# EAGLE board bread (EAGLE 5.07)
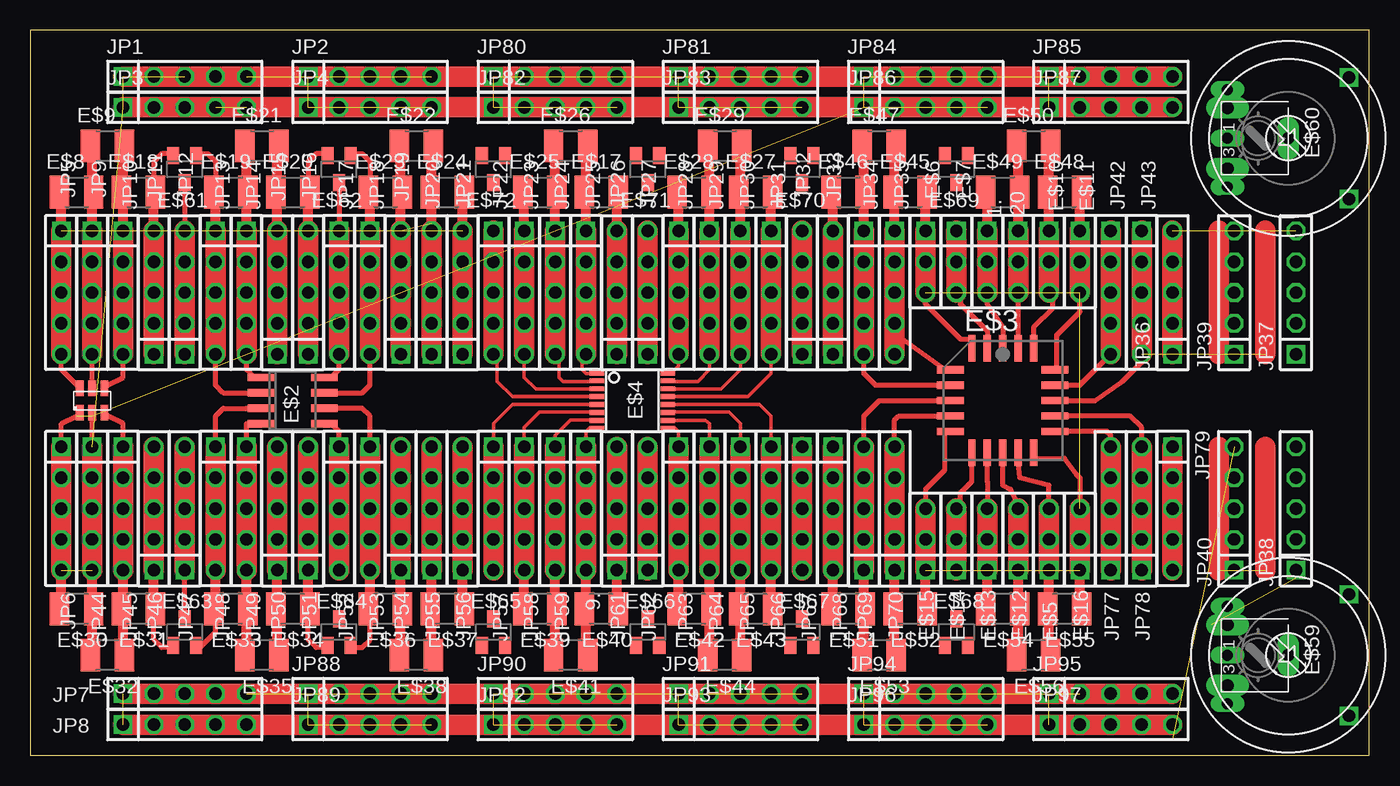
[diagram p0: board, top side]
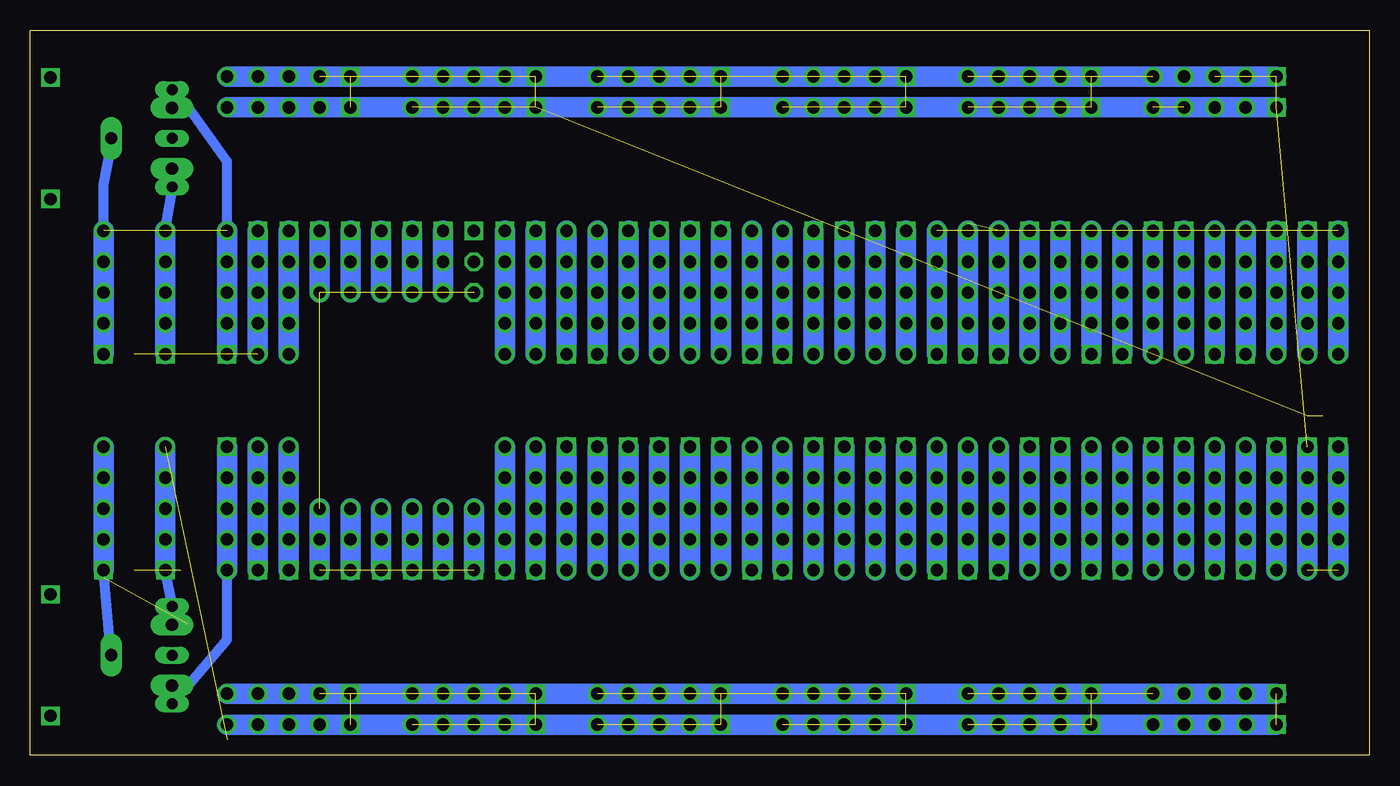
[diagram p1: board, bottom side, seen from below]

Size 110.16 x 59.68 mm. Coordinates in mm from the lower left corner, seen from the top.
Outline: 0,0 110.16,0 110.16,59.68 0,59.68 0,0
Copper layers (1*16): Top 0.035mm / dielectric 1.5mm / Bottom 0.035mm
Design rules "default": minimum track width 10mil, minimum drill 24mil, track to track 8mil, track to pad 8mil, pad to pad 8mil, via to via 8mil, smd to smd 8mil, copper to edge 40mil, drill to drill 8mil, minimum pad ring 10mil, minimum via ring 8mil, stop-mask expansion 4mil, vias tented up to drill 0mil, thermal gap 10mil

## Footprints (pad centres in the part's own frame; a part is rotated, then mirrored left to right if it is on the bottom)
1X03 = drill 1.016 square: 1 -2.54,0 | drill 1.016 octagon: 2 0,0; 3 2.54,0
1X05 = drill 1.016 square: 1 -5.08,0 | drill 1.016 octagon: 2 -2.54,0; 3 0,0; 4 2.54,0; 5 5.08,0
SOT23-6 = smd 0.635 x 1.27: 1 -1.016,-1.016; 2 0,-1.016; 3 1.016,-1.016; 4 1.016,1.016; 5 0,1.016; 6 -1.016,1.016
SO08 = smd 0.6 x 2.2: 1 -1.905,-2.6; 2 -0.635,-2.6; 3 0.635,-2.6; 4 1.905,-2.6; 5 1.905,2.6; 6 0.635,2.6; 7 -0.635,2.6; 8 -1.905,2.6
PLCC20S = smd 0.6 x 2.2: 1 0,4.3; 2 -1.27,4.3; 3 -2.54,4.3; 9 -2.54,-4.3; 10 -1.27,-4.3; 11 0,-4.3; 12 1.27,-4.3; 13 2.54,-4.3; 19 2.54,4.3; 20 1.27,4.3 | smd 2.2 x 0.6: 4 -4.3,2.54; 5 -4.3,1.27; 6 -4.3,0; 7 -4.3,-1.27; 8 -4.3,-2.54; 14 4.3,-2.54; 15 4.3,-1.27; 16 4.3,0; 17 4.3,1.27; 18 4.3,2.54
SSOP16 = smd 0.4 x 1.2: 1 -2.275,-2.925; 2 -1.625,-2.925; 3 -0.975,-2.925; 4 -0.325,-2.925; 5 0.325,-2.925; 6 0.975,-2.925; 7 1.625,-2.925; 8 2.275,-2.925; 9 2.275,2.925; 10 1.625,2.925; 11 0.975,2.925; 12 0.325,2.925; 13 -0.325,2.925; 14 -0.975,2.925; 15 -1.625,2.925; 16 -2.275,2.925
R1210 = smd 1.6 x 2.7: 1 -1.4,0; 2 1.4,0
RANDL = drill 0.9 long: A -4,5; E 4,5; S 0,5 | drill 1 square: P$1 -5,-5; P$2 5,-5
EVND8AA = drill 1 pad 1.778 long: A -2.5,-2.5; E 2.5,-2.5; S 0,2.5
SOT23 = smd 1 x 1.4: 1 -0.95,-1.1; 2 0.95,-1.1; 3 0,1.1

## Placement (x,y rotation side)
1.  [1X03]  78.74,40.64 270 top
9.  [1X05]  45.72,20.32 270 top
20  [1X03]  81.28,40.64 270 top
E$1  [SOT23-6]  5.08,29.21 0 top
E$2  [SO08]  21.59,29.21 270 top
E$3  [PLCC20S]  80.01,29.21 0 top
E$4  [SSOP16]  49.53,29.21 270 top
E$5  [1X03]  83.82,17.78 90 top
E$6  [1X03]  73.66,40.64 270 top
E$7  [1X03]  76.2,40.64 270 top
E$8  [R1210]  3.81,46.35 0 top
E$9  [R1210]  6.35,50.16 0 top
E$10  [1X03]  83.82,40.64 270 top
E$11  [1X03]  86.36,40.64 270 top
E$12  [1X03]  81.28,17.78 90 top
E$13  [1X03]  78.74,17.78 90 top
E$14  [1X03]  76.2,17.78 90 top
E$15  [1X03]  73.66,17.78 90 top
E$16  [1X03]  86.36,17.78 90 top
E$17  [R1210]  46.99,46.35 0 top
E$18  [R1210]  8.89,46.35 0 top
E$19  [R1210]  16.51,46.35 0 top
E$20  [R1210]  21.59,46.35 0 top
E$21  [R1210]  19.05,50.16 0 top
E$22  [R1210]  31.75,50.16 0 top
E$23  [R1210]  29.21,46.35 0 top
E$24  [R1210]  34.29,46.35 0 top
E$25  [R1210]  41.91,46.35 0 top
E$26  [R1210]  44.45,50.16 0 top
E$27  [R1210]  59.69,46.35 0 top
E$28  [R1210]  54.61,46.35 0 top
E$29  [R1210]  57.15,50.16 0 top
E$30  [R1210]  3.81,12.06 180 top
E$31  [R1210]  8.89,12.06 180 top
E$32  [R1210]  6.35,8.26 180 top
E$33  [R1210]  16.51,12.06 180 top
E$34  [R1210]  21.59,12.06 180 top
E$35  [R1210]  19.05,8.26 180 top
E$36  [R1210]  29.21,12.06 180 top
E$37  [R1210]  34.29,12.06 180 top
E$38  [R1210]  31.75,8.26 180 top
E$39  [R1210]  41.91,12.06 180 top
E$40  [R1210]  46.99,12.06 180 top
E$41  [R1210]  44.45,8.26 180 top
E$42  [R1210]  54.61,12.06 180 top
E$43  [R1210]  59.69,12.06 180 top
E$44  [R1210]  57.15,8.26 180 top
E$45  [R1210]  72.39,46.35 0 top
E$46  [R1210]  67.31,46.35 0 top
E$47  [R1210]  69.85,50.16 0 top
E$48  [R1210]  85.09,46.35 0 top
E$49  [R1210]  80.01,46.35 0 top
E$50  [R1210]  82.55,50.16 0 top
E$51  [R1210]  67.31,12.06 180 top
E$52  [R1210]  72.39,12.06 180 top
E$53  [R1210]  69.85,8.26 180 top
E$54  [R1210]  80.01,12.06 180 top
E$55  [R1210]  85.09,12.06 180 top
E$56  [R1210]  82.55,8.26 180 top
E$57  [RANDL]  103.5,50.8 90 top
E$58  [RANDL]  103.5,8.26 90 top
E$59  [EVND8AA]  101.02,8.26 270 top
E$60  [EVND8AA]  101.02,50.8 270 top
E$61  [SOT23]  12.7,48.26 180 top
E$62  [SOT23]  25.4,48.26 180 top
E$63  [SOT23]  12.7,10.16 0 top
E$64  [SOT23]  25.4,10.16 0 top
E$65  [SOT23]  38.1,10.16 0 top
E$66  [SOT23]  50.8,10.16 0 top
E$67  [SOT23]  63.5,10.16 0 top
E$68  [SOT23]  76.2,10.16 0 top
E$69  [SOT23]  76.2,48.26 180 top
E$70  [SOT23]  63.5,48.26 180 top
E$71  [SOT23]  50.8,48.26 180 top
E$72  [SOT23]  38.1,48.26 180 top
JP1  [1X05]  12.7,55.88 0 top
JP2  [1X05]  27.94,55.88 0 top
JP3  [1X05]  12.7,53.34 0 top
JP4  [1X05]  27.94,53.34 0 top
JP5  [1X05]  2.54,38.1 270 top
JP6  [1X05]  2.54,20.32 270 top
JP7  [1X05]  12.7,5.08 0 top
JP8  [1X05]  12.7,2.54 0 top
JP9  [1X05]  5.08,38.1 270 top
JP10  [1X05]  7.62,38.1 270 top
JP11  [1X05]  10.16,38.1 90 top
JP12  [1X05]  12.7,38.1 90 top
JP13  [1X05]  15.24,38.1 270 top
JP14  [1X05]  17.78,38.1 270 top
JP15  [1X05]  20.32,38.1 90 top
JP16  [1X05]  22.86,38.1 90 top
JP17  [1X05]  25.4,38.1 270 top
JP18  [1X05]  27.94,38.1 270 top
JP19  [1X05]  30.48,38.1 90 top
JP20  [1X05]  33.02,38.1 90 top
JP21  [1X05]  35.56,38.1 90 top
JP22  [1X05]  38.1,38.1 270 top
JP23  [1X05]  40.64,38.1 270 top
JP24  [1X05]  43.18,38.1 270 top
JP25  [1X05]  45.72,38.1 270 top
JP26  [1X05]  48.26,38.1 90 top
JP27  [1X05]  50.8,38.1 90 top
JP28  [1X05]  53.34,38.1 270 top
JP29  [1X05]  55.88,38.1 270 top
JP30  [1X05]  58.42,38.1 270 top
JP31  [1X05]  60.96,38.1 270 top
JP32  [1X05]  63.5,38.1 90 top
JP33  [1X05]  66.04,38.1 90 top
JP34  [1X05]  68.58,38.1 270 top
JP35  [1X05]  71.12,38.1 270 top
JP36  [1X05]  93.98,38.1 90 top
JP37  [1X05]  104.14,38.1 90 top
JP38  [1X05]  104.14,20.32 90 top
JP39  [1X05]  99.06,38.1 90 top
JP40  [1X05]  99.06,20.32 90 top
JP42  [1X05]  88.9,38.1 270 top
JP43  [1X05]  91.44,38.1 270 top
JP44  [1X05]  5.08,20.32 270 top
JP45  [1X05]  7.62,20.32 270 top
JP46  [1X05]  10.16,20.32 90 top
JP47  [1X05]  12.7,20.32 90 top
JP48  [1X05]  15.24,20.32 270 top
JP49  [1X05]  17.78,20.32 270 top
JP50  [1X05]  20.32,20.32 90 top
JP51  [1X05]  22.86,20.32 90 top
JP52  [1X05]  25.4,20.32 270 top
JP53  [1X05]  27.94,20.32 270 top
JP54  [1X05]  30.48,20.32 90 top
JP55  [1X05]  33.02,20.32 90 top
JP56  [1X05]  35.56,20.32 90 top
JP57  [1X05]  38.1,20.32 270 top
JP58  [1X05]  40.64,20.32 270 top
JP59  [1X05]  43.18,20.32 270 top
JP61  [1X05]  48.26,20.32 90 top
JP62  [1X05]  50.8,20.32 90 top
JP63  [1X05]  53.34,20.32 270 top
JP64  [1X05]  55.88,20.32 270 top
JP65  [1X05]  58.42,20.32 270 top
JP66  [1X05]  60.96,20.32 270 top
JP67  [1X05]  63.5,20.32 270 top
JP68  [1X05]  66.04,20.32 270 top
JP69  [1X05]  68.58,20.32 90 top
JP70  [1X05]  71.12,20.32 90 top
JP77  [1X05]  88.9,20.32 90 top
JP78  [1X05]  91.44,20.32 90 top
JP79  [1X05]  93.98,20.32 270 top
JP80  [1X05]  43.18,55.88 0 top
JP81  [1X05]  58.42,55.88 0 top
JP82  [1X05]  43.18,53.34 0 top
JP83  [1X05]  58.42,53.34 0 top
JP84  [1X05]  73.66,55.88 0 top
JP85  [1X05]  88.9,55.88 0 top
JP86  [1X05]  73.66,53.34 0 top
JP87  [1X05]  88.9,53.34 0 top
JP88  [1X05]  27.94,5.08 0 top
JP89  [1X05]  27.94,2.54 0 top
JP90  [1X05]  43.18,5.08 0 top
JP91  [1X05]  58.42,5.08 0 top
JP92  [1X05]  43.18,2.54 0 top
JP93  [1X05]  58.42,2.54 0 top
JP94  [1X05]  73.66,5.08 0 top
JP95  [1X05]  88.9,5.08 0 top
JP96  [1X05]  73.66,2.54 0 top
JP97  [1X05]  88.9,2.54 0 top

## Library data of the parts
1. 9. 20 E$5-E$7 E$10-E$16 JP1-JP40 JP42-JP59 JP61-JP70 JP77-JP97 = pinhead(2)
E$1 = microchip-5
E$2-E$4 = linear
E$8 E$9 E$17-E$56 = rcl
E$57-E$60 = pot
E$61-E$72 = transistor-npn

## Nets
N$1: JP1.1 JP1.2 JP1.3
N$2: JP2.1 JP2.2
N$3: JP3.4 JP3.5
N$76: JP80.1 JP80.2 JP80.3
N$77: JP81.1 JP81.2
N$78: JP82.4 JP82.5
N$80: JP84.1 JP84.2 JP84.3
N$81: JP85.1 JP85.2
N$82: JP86.4 JP86.5
N$84: JP88.1 JP88.2
N$86: JP90.1 JP90.2 JP90.3
N$87: JP91.1 JP91.2
N$88: JP92.4 JP92.5
N$90: JP94.1 JP94.2 JP94.3
N$91: JP95.1 JP95.2
N$92: JP96.4 JP96.5
S$25: 20.3
S$30: E$7.3
S$31: E$6.3
S$42: E$5.1
S$43: E$14.3

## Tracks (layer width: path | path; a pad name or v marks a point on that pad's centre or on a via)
N$1  (2 unrouted)
N$2  (1 unrouted)
N$3  (1 unrouted)
N$4  (4 unrouted)
  Top 0.406: 3.81,30.48 2.54,31.75 2.54,33.02 | 26.67,49.53 27.3,49.53 27.94,48.9 27.94,46.35 | 24.13,49.53 23.5,49.53 22.86,48.9 22.86,46.35 | 13.97,49.53 14.61,49.53 15.24,48.9 15.24,46.35
  Top 0.813: 2.54,43.18 2.54,46.35 | 15.24,43.18 15.24,46.35 | 22.86,43.18 22.86,46.35 | 27.94,43.18 27.94,46.35 | 35.56,43.18 35.56,46.35
  Top 1.676: 2.54,33.02 2.54,43.18
N$5  (4 unrouted)
  Top 0.406: 5.08,30.48 5.08,33.02
  Top 0.813: 5.08,43.18 5.08,49.53 | 17.78,43.18 17.78,49.53 | 20.32,43.18 20.32,49.53 | 30.48,43.18 30.48,49.53 | 33.02,43.81 33.02,50.16
  Top 1.676: 5.08,33.02 5.08,43.18
N$6
  Top 0.406: 6.35,30.48 7.62,31.11 7.62,33.02
  Top 0.813: 7.62,43.18 7.62,49.53
  Top 1.676: 7.62,33.02 7.62,43.18
N$7  (3 unrouted)
  Top 0.406: 85.09,29.21 87.63,29.21 89.85,30.8 91.44,32.38 91.44,33.02
  Top 1.676: 91.44,33.02 91.44,43.18 | 93.98,33.02 93.98,43.18 | 97.79,33.02 97.79,43.18 | 101.6,33.02 101.6,43.18
N$8
  Top 1.676: 88.9,33.02 88.9,43.18
N$9
  Top 0.813: 40.64,43.18 40.64,46.35
N$10
  Top 0.813: 43.18,43.18 43.18,49.53
N$11
  Top 0.813: 45.72,43.18 45.72,49.53
N$12
  Top 0.813: 48.26,43.18 48.26,46.35
N$13
  Top 0.813: 53.34,43.18 53.34,46.35
N$14
  Top 0.813: 55.88,43.18 55.88,49.53
N$15
  Top 0.305: 71.44,37.15 71.12,37.47 71.12,38.1
  Top 0.406: 75.25,31.75 71.75,34.29 71.44,37.15
  Top 1.676: 71.12,33.02 71.12,38.1 71.12,43.18
N$16
  Top 0.813: 58.42,43.18 58.42,49.53
N$17
  Top 0.813: 60.96,43.18 60.96,46.35
N$18
  Top 0.406: 12.06,8.89 10.79,8.89 10.16,9.53 10.16,12.7
  Top 0.813: 10.16,12.06 10.16,12.7 10.16,15.24
N$19
  Top 1.676: 60.96,33.02 60.96,43.18
N$20
  Top 0.305: 52.7,30.16 56.83,30.16 58.42,31.75 58.42,33.02
  Top 1.676: 58.42,33.02 58.42,43.18
N$21
  Top 0.305: 52.7,30.8 54.93,30.8 55.88,31.75 55.88,33.02
  Top 1.676: 55.88,33.02 55.88,43.18
N$22
  Top 1.676: 53.34,33.02 53.34,43.18
N$23
  Top 1.676: 50.8,33.02 50.8,43.18
N$24
  Top 1.676: 48.26,33.02 48.26,43.18
N$25
  Top 0.305: 46.04,31.43 45.72,31.43 45.4,31.75 45.4,32.7 45.72,33.02
  Top 1.676: 45.72,33.02 45.72,43.18
N$26
  Top 0.305: 46.04,30.8 43.81,30.8 43.5,31.11 43.5,32.7 43.18,33.02
  Top 1.676: 43.18,33.02 43.18,43.18
N$27
  Top 0.305: 46.04,30.16 41.59,30.16 40.64,31.11 40.64,33.02
  Top 1.676: 40.64,33.02 40.64,43.18
N$28
  Top 0.305: 46.35,29.53 39.69,29.53 38.42,30.8 38.42,32.7 38.1,33.02
  Top 1.676: 38.1,33.02 38.1,43.18
N$29
  Top 1.676: 35.56,33.02 35.56,43.18
N$30
  Top 1.676: 33.02,33.02 33.02,43.18
N$31
  Top 1.676: 30.48,33.02 30.48,43.18
N$32
  Top 0.406: 24.77,29.84 27.3,29.84 27.94,30.48 27.94,33.02
  Top 1.676: 27.94,33.02 27.94,43.18
N$33
  Top 0.406: 24.77,31.11 25.4,31.75 25.4,33.02 | 25.4,46.99 25.4,43.18
  Top 1.676: 25.4,33.02 25.4,43.18
N$34
  Top 1.676: 22.86,33.02 22.86,43.18
N$35
  Top 1.676: 20.32,33.02 20.32,43.18
N$36
  Top 0.406: 18.41,31.11 17.78,31.75 17.78,33.02
  Top 1.676: 17.78,33.02 17.78,43.18
N$37
  Top 0.406: 18.41,29.84 15.88,29.84 15.24,30.48 15.24,33.02
  Top 1.676: 15.24,33.02 15.24,43.18
N$38
  Top 0.406: 12.7,46.35 12.7,43.18
  Top 1.676: 12.7,33.02 12.7,43.18
N$39
  Top 0.406: 11.43,49.53 10.79,49.53 10.16,48.9 10.16,45.72
  Top 0.813: 10.16,43.18 10.16,45.72 10.16,46.35
  Top 1.676: 10.16,33.02 10.16,43.18
N$40  (5 unrouted)
  Top 0.406: 3.81,27.94 2.54,27.3 2.54,25.4 | 5.08,25.4 5.08,27.94
  Top 1.676: 5.08,15.24 5.08,25.4 | 83.82,55.88 93.98,55.88 | 83.82,53.34 93.98,53.34 | 68.58,53.34 78.74,53.34 | 68.58,55.88 78.74,55.88 | 2.54,15.24 2.54,25.4
N$41
  Top 1.676: 93.98,15.24 93.98,25.4
N$42
  Top 0.406: 85.41,27.94 90.49,27.94 91.44,26.99 91.44,25.08
  Top 1.676: 91.44,15.24 91.44,25.08 91.44,25.4
N$43
  Top 0.406: 85.41,26.67 88.58,26.67 88.9,26.35 88.9,25.4
  Top 1.676: 88.9,15.24 88.9,25.4
N$44
  Top 0.813: 7.62,8.89 7.62,15.24
N$45
  Top 0.406: 82.55,24.45 85.09,24.45 86.04,23.18 86.36,22.86 86.36,20.64
N$46
  Top 0.813: 5.08,8.89 5.08,15.24
N$47
  Top 0.406: 80.01,23.81 80.01,22.23 80.64,21.91 81.28,20.64
N$48
  Top 0.406: 78.74,24.13 78.74,22.54 78.74,20.64
N$49
  Top 0.813: 2.54,12.06 2.54,15.24
N$50
  Top 0.305: 71.12,25.4 71.12,25.72
  Top 0.406: 74.93,27.94 71.44,27.94 71.12,27.62 71.12,25.72
  Top 1.676: 71.12,15.24 71.12,25.4
N$51
  Top 0.406: 74.93,29.21 69.85,29.21 68.58,27.94 68.58,25.4
  Top 1.676: 68.58,15.24 68.58,25.4
N$52
  Top 1.676: 66.04,15.24 66.04,25.4
N$53
  Top 1.676: 63.5,15.24 63.5,25.4
N$54
  Top 1.676: 60.96,15.24 60.96,25.4
N$55
  Top 0.305: 52.39,28.26 57.47,28.26 58.42,27.3 58.42,25.4
  Top 1.676: 58.42,15.24 58.42,25.4
N$56
  Top 0.305: 52.7,27.56 55.56,27.56 55.88,27.3 55.88,25.4
  Top 1.676: 55.88,15.24 55.88,25.4
N$57
  Top 0.305: 53.02,26.99 53.34,26.67 53.34,25.08
  Top 1.676: 53.34,15.24 53.34,25.08 53.34,25.4
N$58
  Top 1.676: 50.8,15.24 50.8,25.4
N$59
  Top 1.676: 48.26,15.24 48.26,25.4
N$60
  Top 0.305: 46.35,26.99 46.04,26.99 45.72,26.67 45.72,25.4
  Top 1.676: 45.72,15.24 45.72,25.4
N$61
  Top 0.305: 46.04,27.62 44.45,27.62 43.18,26.35 43.18,25.4
  Top 1.676: 43.18,15.24 43.18,25.4
N$62
  Top 0.305: 46.04,28.26 41.91,28.26 40.64,26.99 40.64,25.4
  Top 1.676: 40.64,15.24 40.64,25.4
N$63
  Top 0.305: 46.04,28.89 39.69,28.89 38.1,27.3 38.1,25.4
  Top 1.676: 38.1,15.24 38.1,25.4
N$64
  Top 1.676: 35.56,15.24 35.56,25.4
N$65
  Top 1.676: 33.02,15.24 33.02,25.4
N$66
  Top 1.676: 30.48,15.24 30.48,25.4
N$67
  Top 0.406: 24.77,28.57 27.3,28.57 27.94,27.94 27.94,25.4
  Top 1.676: 27.94,15.24 27.94,25.4
N$68
  Top 0.406: 24.77,27.3 25.4,26.67 25.4,25.4
  Top 1.676: 25.4,15.24 25.4,25.4
N$69
  Top 1.676: 22.86,15.24 22.86,25.4
N$70
  Top 1.676: 20.32,15.24 20.32,25.4
N$71
  Top 0.406: 17.78,25.4 17.78,27.3
  Top 1.676: 17.78,15.24 17.78,25.4
N$72
  Top 0.406: 17.78,28.57 15.88,28.57 15.24,27.94 15.24,25.4
  Top 1.676: 15.24,15.24 15.24,25.4
N$73
  Top 0.406: 12.7,11.43 12.7,15.24
  Top 1.676: 12.7,15.24 12.7,25.4
N$74
  Top 1.676: 10.16,15.24 10.16,25.4
N$75
  Top 0.406: 6.35,27.94 7.62,27.3 7.62,25.4
  Top 1.676: 7.62,15.24 7.62,25.4
N$76  (2 unrouted)
N$77  (1 unrouted)
N$78  (1 unrouted)
N$79  (3 unrouted)
  Top 1.676: 53.34,55.88 63.5,55.88 | 53.34,53.34 63.5,53.34 | 38.1,53.34 48.26,53.34 | 38.1,55.88 48.26,55.88
N$80  (2 unrouted)
N$81  (1 unrouted)
N$82  (1 unrouted)
N$83  (3 unrouted)
  Top 1.676: 22.86,55.88 33.02,55.88 | 22.86,53.34 33.02,53.34 | 7.62,53.34 17.78,53.34 | 7.62,55.88 17.78,55.88
N$84  (1 unrouted)
N$85  (3 unrouted)
  Top 1.676: 68.58,2.54 78.74,2.54 | 68.58,5.08 78.74,5.08 | 83.82,5.08 93.98,5.08 | 83.82,2.54 93.98,2.54
N$86  (2 unrouted)
N$87  (1 unrouted)
N$88  (1 unrouted)
N$89  (3 unrouted)
  Top 1.676: 53.34,5.08 63.5,5.08 | 53.34,2.54 63.5,2.54 | 38.1,2.54 48.26,2.54 | 38.1,5.08 48.26,5.08
N$90  (2 unrouted)
N$91  (1 unrouted)
N$92  (1 unrouted)
N$93  (3 unrouted)
  Top 1.676: 22.86,5.08 33.02,5.08 | 22.86,2.54 33.02,2.54 | 7.62,2.54 17.78,2.54 | 7.62,5.08 17.78,5.08
N$94
  Bottom 1.676: 2.54,33.02 2.54,43.18
N$95
  Bottom 1.676: 5.08,33.02 5.08,43.18
N$96
  Bottom 1.676: 7.62,33.02 7.62,43.18
N$97
  Bottom 1.676: 10.16,33.02 10.16,43.18
N$98
  Bottom 1.676: 12.7,33.02 12.7,43.18
N$99
  Bottom 1.676: 15.24,33.02 15.24,43.18
N$100
  Bottom 1.676: 17.78,33.02 17.78,43.18
N$101
  Bottom 1.676: 20.32,33.02 20.32,43.18
N$102
  Bottom 1.676: 22.86,33.02 22.86,43.18
N$103
  Bottom 1.676: 25.4,33.02 25.4,43.18
N$104
  Bottom 1.676: 27.94,33.02 27.94,43.18
N$105
  Bottom 1.676: 30.48,33.02 30.48,43.18
N$106
  Bottom 1.676: 33.02,33.02 33.02,43.18
N$107
  Bottom 1.676: 35.56,33.02 35.56,43.18
N$108
  Bottom 1.676: 38.1,33.02 38.1,43.18
N$109
  Bottom 1.676: 40.64,33.02 40.64,43.18
N$110
  Bottom 1.676: 43.18,33.02 43.18,43.18
N$111
  Bottom 1.676: 45.72,33.02 45.72,43.18
N$112
  Bottom 1.676: 48.26,33.02 48.26,43.18
N$113
  Bottom 1.676: 50.8,33.02 50.8,43.18
N$114
  Bottom 1.676: 53.34,33.02 53.34,43.18
N$115
  Bottom 1.676: 55.88,33.02 55.88,43.18
N$116
  Bottom 1.676: 58.42,33.02 58.42,43.18
N$117
  Bottom 1.676: 60.96,33.02 60.96,43.18
N$118
  Bottom 1.676: 63.5,33.02 63.5,43.18
N$119
  Bottom 1.676: 66.04,33.02 66.04,43.18
N$120
  Bottom 1.676: 68.58,33.02 68.58,43.18
N$121
  Bottom 1.676: 71.12,33.02 71.12,43.18
N$122
  Top 0.406: 24.13,8.89 23.5,8.89 22.86,9.53 22.86,12.06
  Top 0.813: 22.86,12.06 22.86,15.24
N$123
  Top 0.813: 20.32,8.89 20.32,15.24
N$124
  Top 0.813: 17.78,8.89 17.78,15.24
N$125
  Top 0.406: 13.34,8.89 13.97,8.89 15.24,10.16 15.24,12.06
  Top 0.813: 15.24,12.06 15.24,15.24
N$126
  Top 0.813: 35.56,12.06 35.56,15.24
N$127
  Top 0.813: 33.02,8.89 33.02,15.24
N$128
  Bottom 1.676: 88.9,33.02 88.9,43.18
N$129  (3 unrouted)
  Bottom 0.813: 97.16,53.34 93.98,48.9 93.98,42.55 | 103.5,50.16 104.14,46.99 104.14,43.18 | 99.06,43.18 98.42,46.99
  Bottom 1.676: 104.14,33.02 104.14,43.18 | 93.98,43.18 93.98,42.55 93.98,33.02 | 91.44,33.02 91.44,43.18 | 99.06,33.02 99.06,43.18
N$130  (5 unrouted)
  Bottom 1.676: 5.08,15.24 5.08,25.4 | 7.62,55.88 17.78,55.88 | 7.62,53.34 17.78,53.34 | 22.86,53.34 33.02,53.34 | 22.86,55.88 33.02,55.88 | 2.54,15.24 2.54,25.4
N$131
  Bottom 1.676: 7.62,15.24 7.62,25.4
N$132
  Bottom 1.676: 10.16,15.24 10.16,25.4
N$133
  Bottom 1.676: 12.7,15.24 12.7,25.4
N$134
  Bottom 1.676: 15.24,15.24 15.24,25.4
N$135
  Bottom 1.676: 17.78,15.24 17.78,25.4
N$136
  Bottom 1.676: 20.32,15.24 20.32,25.4
N$137
  Bottom 1.676: 22.86,15.24 22.86,25.4
N$138
  Bottom 1.676: 25.4,15.24 25.4,25.4
N$139
  Bottom 1.676: 27.94,15.24 27.94,25.4
N$140
  Bottom 1.676: 30.48,15.24 30.48,25.4
N$141
  Bottom 1.676: 33.02,15.24 33.02,25.4
N$142
  Bottom 1.676: 35.56,15.24 35.56,25.4
N$143
  Bottom 1.676: 38.1,15.24 38.1,25.4
N$144
  Bottom 1.676: 40.64,15.24 40.64,25.4
N$145
  Bottom 1.676: 43.18,15.24 43.18,25.4
N$146
  Bottom 1.676: 45.72,15.24 45.72,25.4
N$147
  Bottom 1.676: 48.26,15.24 48.26,25.4
N$148
  Bottom 1.676: 50.8,15.24 50.8,25.4
N$149
  Bottom 1.676: 53.34,15.24 53.34,25.4
N$150
  Bottom 1.676: 55.88,15.24 55.88,25.4
N$151
  Bottom 1.676: 58.42,15.24 58.42,25.4
N$152
  Bottom 1.676: 60.96,15.24 60.96,25.4
N$153
  Bottom 1.676: 63.5,15.24 63.5,25.4
N$154
  Bottom 1.676: 66.04,15.24 66.04,25.4
N$155
  Bottom 1.676: 68.58,15.24 68.58,25.4
N$156
  Bottom 1.676: 71.12,15.24 71.12,25.4
N$157
  Top 0.813: 30.48,8.89 30.48,15.24
N$158
  Top 0.406: 26.67,8.89 27.3,8.89 27.94,9.53 27.94,12.06
  Top 0.813: 27.94,12.06 27.94,15.24
N$159
  Top 0.813: 48.26,12.06 48.26,15.24
N$160
  Top 0.813: 45.72,8.89 45.72,15.24
N$161  (22 unrouted)
  Top 1.676: 73.66,38.1 73.66,43.18 | 76.2,38.1 76.2,43.18 | 78.74,38.1 78.74,43.18 | 81.28,38.1 81.28,43.18 | 86.36,38.1 86.36,43.18 | 86.36,15.24 86.36,20.32 | 83.82,15.24 83.82,20.32 | 81.28,15.24 81.28,20.32 | 78.74,15.24 78.74,20.32 | 76.2,15.24 76.2,20.32 | 73.66,15.24 73.66,20.32 | 83.82,38.1 83.82,43.18 83.82,38.1
  Bottom 1.676: 83.82,15.24 83.82,20.32 | 81.28,15.24 81.28,20.32 | 78.74,15.24 78.74,20.32 | 76.2,15.24 76.2,20.32 | 73.66,15.24 73.66,20.32 | 86.36,15.24 86.36,20.32 | 86.36,38.1 86.36,43.18 | 83.82,38.1 83.82,43.18 | 81.28,38.1 81.28,43.18 | 78.74,38.1 78.74,43.18 | 76.2,38.1 76.2,43.18
N$162
  Top 0.813: 43.18,8.89 43.18,15.24
N$163
  Top 0.813: 40.64,12.06 40.64,15.24
N$164
  Bottom 1.676: 91.44,15.24 91.44,25.4 | 88.9,15.24 88.9,25.4
N$165
  Bottom 0.813: 97.16,5.71 93.98,9.53 93.98,15.24
  Bottom 1.676: 93.98,15.24 93.98,25.4
N$166  (3 unrouted)
  Bottom 1.676: 38.1,55.88 48.26,55.88 | 38.1,53.34 48.26,53.34 | 53.34,53.34 63.5,53.34 | 53.34,55.88 63.5,55.88
N$167  (3 unrouted)
  Bottom 1.676: 68.58,55.88 78.74,55.88 | 68.58,53.34 78.74,53.34 | 83.82,53.34 93.98,53.34 | 83.82,55.88 93.98,55.88
N$168  (3 unrouted)
  Bottom 1.676: 22.86,2.54 33.02,2.54 | 22.86,5.08 33.02,5.08 | 7.62,5.08 17.78,5.08 | 7.62,2.54 17.78,2.54
N$169  (3 unrouted)
  Bottom 1.676: 38.1,5.08 48.26,5.08 | 38.1,2.54 48.26,2.54 | 53.34,2.54 63.5,2.54 | 53.34,5.08 63.5,5.08
N$170  (3 unrouted)
  Bottom 1.676: 68.58,5.08 78.74,5.08 | 68.58,2.54 78.74,2.54 | 83.82,2.54 93.98,2.54 | 83.82,5.08 93.98,5.08
N$171
  Top 0.813: 60.96,12.06 60.96,15.24
N$172
  Top 0.813: 58.42,8.89 58.42,15.24
N$173
  Top 0.813: 55.88,8.89 55.88,15.24
N$174
  Top 0.813: 53.34,12.06 53.34,15.24
N$175
  Top 0.813: 66.04,43.18 66.04,46.35
N$176
  Top 0.813: 68.58,43.18 68.58,49.53
N$177
  Top 0.813: 71.12,43.18 71.12,49.53
N$178
  Top 0.813: 73.66,43.18 73.66,46.35
N$179
  Top 0.813: 78.74,43.18 78.74,46.35
N$180
  Top 0.813: 81.28,43.18 81.28,49.53
N$181
  Top 0.813: 83.82,43.18 83.82,49.53
N$182
  Top 0.813: 86.36,43.18 86.36,46.35
N$183
  Top 0.813: 73.66,12.06 73.66,15.24
N$184
  Top 0.813: 71.12,8.89 71.12,15.24
N$185
  Top 0.813: 68.58,8.89 68.58,15.24
N$186
  Top 0.813: 66.04,12.06 66.04,15.24
N$187
  Top 0.813: 86.36,12.06 86.36,15.24
N$188
  Top 0.813: 83.82,8.89 83.82,15.24
N$189
  Top 0.813: 81.28,8.89 81.28,15.24
N$190
  Top 0.813: 78.74,12.06 78.74,15.24
N$191  (1 unrouted)
  Top 1.676: 97.79,15.24 97.79,25.4 | 101.6,15.24 101.6,25.4
N$192  (1 unrouted)
  Bottom 0.813: 103.5,7.62 104.14,14.61 104.14,15.24
  Bottom 1.676: 104.14,25.4 104.14,15.24
S$1
  Top 1.676: 78.74,55.88 83.82,55.88
S$2
  Top 1.676: 78.74,53.34 83.82,53.34
S$3  (1 unrouted)
  Top 1.676: 48.26,55.88 53.34,55.88 | 63.5,55.88 68.58,55.88
S$4  (1 unrouted)
  Top 1.676: 48.26,53.34 53.34,53.34 | 63.5,53.34 68.58,53.34
S$5  (1 unrouted)
  Top 1.676: 17.78,55.88 22.86,55.88 | 33.02,55.88 38.1,55.88
S$6  (1 unrouted)
  Top 1.676: 17.78,53.34 22.86,53.34 | 33.02,53.34 38.1,53.34
S$7
  Top 1.676: 78.74,5.08 83.82,5.08
S$8
  Top 1.676: 78.74,2.54 83.82,2.54
S$9  (1 unrouted)
  Top 1.676: 48.26,5.08 53.34,5.08 | 63.5,5.08 68.58,5.08
S$10  (1 unrouted)
  Top 1.676: 48.26,2.54 53.34,2.54 | 63.5,2.54 68.58,2.54
S$11  (1 unrouted)
  Top 1.676: 17.78,5.08 22.86,5.08 | 33.02,5.08 38.1,5.08
S$12  (1 unrouted)
  Top 1.676: 17.78,2.54 22.86,2.54 | 33.02,2.54 38.1,2.54
S$13
  Bottom 1.676: 17.78,55.88 22.86,55.88
S$14
  Bottom 1.676: 17.78,53.34 22.86,53.34
S$15  (1 unrouted)
  Bottom 1.676: 48.26,55.88 53.34,55.88 | 33.02,55.88 38.1,55.88
S$16  (1 unrouted)
  Bottom 1.676: 48.26,53.34 53.34,53.34 | 33.02,53.34 38.1,53.34
S$17  (1 unrouted)
  Bottom 1.676: 78.74,55.88 83.82,55.88 | 63.5,55.88 68.58,55.88
S$18  (1 unrouted)
  Bottom 1.676: 78.74,53.34 83.82,53.34 | 63.5,53.34 68.58,53.34
S$19
  Bottom 1.676: 17.78,5.08 22.86,5.08
S$20
  Bottom 1.676: 17.78,2.54 22.86,2.54
S$21  (1 unrouted)
  Bottom 1.676: 48.26,5.08 53.34,5.08 | 33.02,5.08 38.1,5.08
S$22  (1 unrouted)
  Bottom 1.676: 48.26,2.54 53.34,2.54 | 33.02,2.54 38.1,2.54
S$23  (1 unrouted)
  Bottom 1.676: 78.74,5.08 83.82,5.08 | 63.5,5.08 68.58,5.08
S$24  (1 unrouted)
  Bottom 1.676: 78.74,2.54 83.82,2.54 | 63.5,2.54 68.58,2.54
S$25
  Top 0.406: 81.28,34.61 20.3
S$26
  Top 1.676: 66.04,33.02 66.04,43.18
S$27
  Top 0.305: 63.5,43.18 63.18,42.86
  Top 1.676: 63.5,33.02 63.5,43.18
S$28
  Top 0.406: 80.01,34.29 80.01,35.24 78.74,37.15 78.74,37.78
S$29
  Top 0.305: 52.7,31.43 53.34,32.07 53.34,32.7 53.66,33.02
S$30
  Top 0.406: 78.74,34.29 78.74,34.92 76.52,37.15 76.52,37.78 E$7.3
S$31
  Top 0.406: 77.47,34.29 76.52,34.29 73.66,37.15 E$6.3
S$32
  Top 0.305: 52.7,29.53 59.05,29.53 60.96,31.43 60.96,32.7
S$33
  Top 0.305: 52.7,28.89 60.01,28.89 60.96,27.94 60.96,25.72
S$34
  Top 0.406: 74.61,30.48 69.53,30.48 68.58,31.43 68.58,33.02
  Top 1.676: 68.58,33.02 68.58,43.18
S$35
  Top 0.406: 82.55,33.97 82.55,35.24 84.14,36.83 84.14,37.47 83.82,37.78
S$36
  Top 0.406: 84.45,32.07 84.45,34.61 86.36,36.51 86.36,37.78
S$37
  Top 0.406: 84.77,30.48 86.36,30.48 88.58,32.7
S$39
  Top 0.305: 91.12,26.04 91.44,25.72
S$40  (1 unrouted)
  Bottom 0.813: 98.42,12.06 99.06,15.24
  Bottom 1.676: 99.06,15.24 99.06,25.4
S$42
  Top 0.406: 81.28,24.13 81.41,22.86 83.82,22.23 E$5.1
S$43
  Top 0.406: 77.47,23.81 77.47,22.54 76.52,21.59 76.52,20.64 E$14.3
S$44
  Top 0.406: 75.25,26.35 75.25,23.5 73.66,21.91 73.66,20.64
